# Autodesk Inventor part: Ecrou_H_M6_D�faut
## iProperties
Created: 2011-01
Part Number: Ecrou_H_M6_D�faut
Document SubType Name: Modeling
Designer: eric
Density: 1 g/cm^3
Mass: 0.289469 g
Surface Area: 3.75991 cm^2
Volume: 0.289469 cm^3
Author: eric
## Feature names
1. Base1
